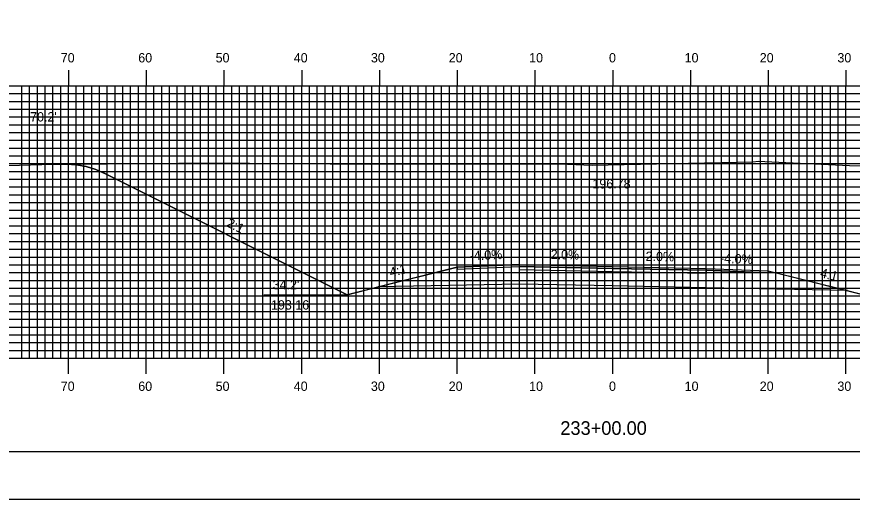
# Model space of a CAD drawing. Extents: x 1799962 to 1800305, y 442591 to 442811.
# Drawn here: x 1800050.9 to 1800158.3, y 442590.5 to 442652.5 of the extents above; entities that cross this region are included whole.
import ezdxf

# ---------------------------------------------------------------- set-up
doc = ezdxf.new("R2010")
doc.units = 0
for name, color, linetype in [('ANNOTATION', 7, 'Continuous'), ('BORDER', 7, 'Continuous'), ('D_Roadway_Centerline', 7, 'Continuous'), ('D_Roadway_Centerline_Text', 7, 'Continuous'), ('D_Roadway_Edge_Shoulder', 7, 'Continuous'), ('D_Roadway_Edge_TW', 7, 'Continuous'), ('D_Roadway_Pavement', 7, 'Continuous'), ('D_Roadway_SlopeLines', 7, 'Continuous'), ('D_Roadway_SubGrade', 7, 'Continuous'), ('D_Text_Standard', 7, 'Continuous'), ('H_V ANNOTATION', 7, 'Continuous'), ('MAJOR', 7, 'Continuous'), ('MINOR', 7, 'Continuous'), ('PDRAIN', 7, 'Continuous'), ('PLOT BOUNDARY', 7, 'Continuous'), ('S_Roadway_Centerline', 7, 'Continuous')]:
    doc.layers.add(name, color=color, linetype=linetype)

msp = doc.modelspace()

# ---------------------------------------------------------------- linework, layer by layer
at = {"layer": 'BORDER'}
msp.add_lwpolyline([(1799977.92, 442596.67), (1800297.92, 442596.67), (1800297.92, 442806.67), (1799977.92, 442806.67)], close=True, dxfattribs=at)
at = {"layer": 'D_Roadway_Centerline'}
msp.add_lwpolyline([(1800057.29, 442633.58), (1800058.54, 442633.51), (1800059.79, 442633.29), (1800061.04, 442632.9), (1800062.29, 442632.35), (1800093.35, 442616.83), (1800097.35, 442617.83), (1800107.52, 442620.37), (1800115.52, 442620.69), (1800127.52, 442620.45), (1800139.52, 442620.21), (1800147.52, 442619.89), (1800157.7, 442617.35), (1800161.7, 442616.35), (1800193.07, 442632.03), (1800194.32, 442632.58), (1800195.57, 442632.97), (1800196.82, 442633.21), (1800198.07, 442633.29)], dxfattribs=at)
at = {"layer": 'D_Roadway_Edge_Shoulder'}
for points in [[(1800115.52, 442620.69), (1800107.52, 442620.37), (1800107.52, 442620.12), (1800115.52, 442620.44)], [(1800139.52, 442620.21), (1800147.52, 442619.89), (1800147.52, 442619.64), (1800139.52, 442619.96)]]:
    msp.add_lwpolyline(points, close=True, dxfattribs=at)
at = {"layer": 'D_Roadway_Edge_TW'}
msp.add_lwpolyline([(1800115.52, 442620.44), (1800115.52, 442620.69), (1800127.52, 442620.45), (1800139.52, 442620.21), (1800139.52, 442619.96), (1800127.52, 442620.2)], close=True, dxfattribs=at)
at = {"layer": 'D_Roadway_Pavement'}
msp.add_lwpolyline([(1800115.52, 442620.02), (1800115.52, 442620.44), (1800127.52, 442620.2), (1800139.52, 442619.96), (1800139.52, 442619.54), (1800127.52, 442619.78)], close=True, dxfattribs=at)
at = {"layer": 'D_Roadway_SlopeLines'}
for points in [[(1800093.35, 442616.83), (1800062.29, 442632.35), (1800061.04, 442632.9), (1800059.79, 442633.29), (1800058.54, 442633.51), (1800057.29, 442633.58)], [(1800107.52, 442620.37), (1800093.35, 442616.83)], [(1800147.52, 442619.89), (1800161.7, 442616.35)]]:
    msp.add_lwpolyline(points, dxfattribs=at)
at = {"layer": 'D_Roadway_SubGrade'}
msp.add_lwpolyline([(1800115.52, 442618.19), (1800097.35, 442617.83), (1800107.52, 442620.37), (1800107.52, 442620.12), (1800115.52, 442620.44), (1800127.52, 442620.2), (1800139.52, 442619.96), (1800147.52, 442619.64), (1800147.52, 442619.89), (1800157.7, 442617.35), (1800139.52, 442617.71), (1800127.52, 442617.95)], close=True, dxfattribs=at)
at = {"layer": 'MAJOR'}
for p, q in [((1800057.52, 442645.67), (1800057.52, 442643.67)), ((1800067.52, 442645.67), (1800067.52, 442643.67)), ((1800077.52, 442645.67), (1800077.52, 442643.67)), ((1800087.52, 442645.67), (1800087.52, 442643.67)), ((1800097.52, 442645.67), (1800097.52, 442643.67)), ((1800107.52, 442645.67), (1800107.52, 442643.67)), ((1800117.52, 442645.67), (1800117.52, 442643.67)), ((1800127.52, 442645.67), (1800127.52, 442643.67)), ((1800137.52, 442645.67), (1800137.52, 442643.67)), ((1800147.52, 442645.67), (1800147.52, 442643.67)), ((1800157.52, 442645.67), (1800157.52, 442643.67)), ((1799987.52, 442643.67), (1800267.52, 442643.67)), ((1799987.52, 442643.67), (1800267.52, 442643.67)), ((1800057.52, 442608.67), (1800057.52, 442643.67)), ((1800067.52, 442608.67), (1800067.52, 442643.67)), ((1800077.52, 442608.67), (1800077.52, 442643.67)), ((1800087.52, 442608.67), (1800087.52, 442643.67)), ((1800097.52, 442608.67), (1800097.52, 442643.67)), ((1800107.52, 442608.67), (1800107.52, 442643.67)), ((1800117.52, 442608.67), (1800117.52, 442643.67)), ((1800127.52, 442608.67), (1800127.52, 442643.67)), ((1800137.52, 442608.67), (1800137.52, 442643.67)), ((1800147.52, 442608.67), (1800147.52, 442643.67)), ((1800157.52, 442608.67), (1800157.52, 442643.67)), ((1799987.52, 442638.67), (1800267.52, 442638.67)), ((1799987.52, 442633.67), (1800267.52, 442633.67)), ((1799987.52, 442628.67), (1800267.52, 442628.67)), ((1799987.52, 442623.67), (1800267.52, 442623.67)), ((1799987.52, 442618.67), (1800267.52, 442618.67)), ((1799987.52, 442613.67), (1800267.52, 442613.67)), ((1799987.52, 442608.67), (1800267.52, 442608.67)), ((1799987.52, 442608.67), (1800267.52, 442608.67)), ((1800057.52, 442606.66), (1800057.52, 442608.67)), ((1800067.52, 442606.66), (1800067.52, 442608.67)), ((1800077.52, 442606.66), (1800077.52, 442608.67)), ((1800087.52, 442606.66), (1800087.52, 442608.67)), ((1800097.52, 442606.66), (1800097.52, 442608.67)), ((1800107.52, 442606.66), (1800107.52, 442608.67)), ((1800117.52, 442606.66), (1800117.52, 442608.67)), ((1800127.52, 442606.66), (1800127.52, 442608.67)), ((1800137.52, 442606.66), (1800137.52, 442608.67)), ((1800147.52, 442606.66), (1800147.52, 442608.67)), ((1800157.52, 442606.66), (1800157.52, 442608.67))]:
    msp.add_line(p, q, dxfattribs=at)
at = {"layer": 'MINOR'}
for p, q in [((1800051.52, 442608.67), (1800051.52, 442643.67)), ((1800052.52, 442608.67), (1800052.52, 442643.67)), ((1800053.52, 442608.67), (1800053.52, 442643.67)), ((1800054.52, 442608.67), (1800054.52, 442643.67)), ((1800055.52, 442608.67), (1800055.52, 442643.67)), ((1800056.52, 442608.67), (1800056.52, 442643.67)), ((1800058.52, 442608.67), (1800058.52, 442643.67)), ((1800059.52, 442608.67), (1800059.52, 442643.67)), ((1800060.52, 442608.67), (1800060.52, 442643.67)), ((1800061.52, 442608.67), (1800061.52, 442643.67)), ((1800062.52, 442608.67), (1800062.52, 442643.67)), ((1800063.52, 442608.67), (1800063.52, 442643.67)), ((1800064.52, 442608.67), (1800064.52, 442643.67)), ((1800065.52, 442608.67), (1800065.52, 442643.67)), ((1800066.52, 442608.67), (1800066.52, 442643.67)), ((1800068.52, 442608.67), (1800068.52, 442643.67)), ((1800069.52, 442608.67), (1800069.52, 442643.67)), ((1800070.52, 442608.67), (1800070.52, 442643.67)), ((1800071.52, 442608.67), (1800071.52, 442643.67)), ((1800072.52, 442608.67), (1800072.52, 442643.67)), ((1800073.52, 442608.67), (1800073.52, 442643.67)), ((1800074.52, 442608.67), (1800074.52, 442643.67)), ((1800075.52, 442608.67), (1800075.52, 442643.67)), ((1800076.52, 442608.67), (1800076.52, 442643.67)), ((1800078.52, 442608.67), (1800078.52, 442643.67)), ((1800079.52, 442608.67), (1800079.52, 442643.67)), ((1800080.52, 442608.67), (1800080.52, 442643.67)), ((1800081.52, 442608.67), (1800081.52, 442643.67)), ((1800082.52, 442608.67), (1800082.52, 442643.67)), ((1800083.52, 442608.67), (1800083.52, 442643.67)), ((1800084.52, 442608.67), (1800084.52, 442643.67)), ((1800085.52, 442608.67), (1800085.52, 442643.67)), ((1800086.52, 442608.67), (1800086.52, 442643.67)), ((1800088.52, 442608.67), (1800088.52, 442643.67)), ((1800089.52, 442608.67), (1800089.52, 442643.67)), ((1800090.52, 442608.67), (1800090.52, 442643.67)), ((1800091.52, 442608.67), (1800091.52, 442643.67)), ((1800092.52, 442608.67), (1800092.52, 442643.67)), ((1800093.52, 442608.67), (1800093.52, 442643.67)), ((1800094.52, 442608.67), (1800094.52, 442643.67)), ((1800095.52, 442608.67), (1800095.52, 442643.67)), ((1800096.52, 442608.67), (1800096.52, 442643.67)), ((1800098.52, 442608.67), (1800098.52, 442643.67)), ((1800099.52, 442608.67), (1800099.52, 442643.67)), ((1800100.52, 442608.67), (1800100.52, 442643.67)), ((1800101.52, 442608.67), (1800101.52, 442643.67)), ((1800102.52, 442608.67), (1800102.52, 442643.67)), ((1800103.52, 442608.67), (1800103.52, 442643.67)), ((1800104.52, 442608.67), (1800104.52, 442643.67)), ((1800105.52, 442608.67), (1800105.52, 442643.67)), ((1800106.52, 442608.67), (1800106.52, 442643.67)), ((1800108.52, 442608.67), (1800108.52, 442643.67)), ((1800109.52, 442608.67), (1800109.52, 442643.67)), ((1800110.52, 442608.67), (1800110.52, 442643.67)), ((1800111.52, 442608.67), (1800111.52, 442643.67)), ((1800112.52, 442608.67), (1800112.52, 442643.67)), ((1800113.52, 442608.67), (1800113.52, 442643.67)), ((1800114.52, 442608.67), (1800114.52, 442643.67)), ((1800115.52, 442608.67), (1800115.52, 442643.67)), ((1800116.52, 442608.67), (1800116.52, 442643.67)), ((1800118.52, 442608.67), (1800118.52, 442643.67)), ((1800119.52, 442608.67), (1800119.52, 442643.67)), ((1800120.52, 442608.67), (1800120.52, 442643.67)), ((1800121.52, 442608.67), (1800121.52, 442643.67)), ((1800122.52, 442608.67), (1800122.52, 442643.67)), ((1800123.52, 442608.67), (1800123.52, 442643.67)), ((1800124.52, 442608.67), (1800124.52, 442643.67)), ((1800125.52, 442608.67), (1800125.52, 442643.67)), ((1800126.52, 442608.67), (1800126.52, 442643.67)), ((1800128.52, 442608.67), (1800128.52, 442643.67)), ((1800129.52, 442608.67), (1800129.52, 442643.67)), ((1800130.52, 442608.67), (1800130.52, 442643.67)), ((1800131.52, 442608.67), (1800131.52, 442643.67)), ((1800132.52, 442608.67), (1800132.52, 442643.67)), ((1800133.52, 442608.67), (1800133.52, 442643.67)), ((1800134.52, 442608.67), (1800134.52, 442643.67)), ((1800135.52, 442608.67), (1800135.52, 442643.67)), ((1800136.52, 442608.67), (1800136.52, 442643.67)), ((1800138.52, 442608.67), (1800138.52, 442643.67)), ((1800139.52, 442608.67), (1800139.52, 442643.67)), ((1800140.52, 442608.67), (1800140.52, 442643.67)), ((1800141.52, 442608.67), (1800141.52, 442643.67)), ((1800142.52, 442608.67), (1800142.52, 442643.67)), ((1800143.52, 442608.67), (1800143.52, 442643.67)), ((1800144.52, 442608.67), (1800144.52, 442643.67)), ((1800145.52, 442608.67), (1800145.52, 442643.67)), ((1800146.52, 442608.67), (1800146.52, 442643.67)), ((1800148.52, 442608.67), (1800148.52, 442643.67)), ((1800149.52, 442608.67), (1800149.52, 442643.67)), ((1800150.52, 442608.67), (1800150.52, 442643.67)), ((1800151.52, 442608.67), (1800151.52, 442643.67)), ((1800152.52, 442608.67), (1800152.52, 442643.67)), ((1800153.52, 442608.67), (1800153.52, 442643.67)), ((1800154.52, 442608.67), (1800154.52, 442643.67)), ((1800155.52, 442608.67), (1800155.52, 442643.67)), ((1800156.52, 442608.67), (1800156.52, 442643.67)), ((1799987.52, 442642.67), (1800267.52, 442642.67)), ((1799987.52, 442641.67), (1800267.52, 442641.67)), ((1799987.52, 442640.67), (1800267.52, 442640.67)), ((1799987.52, 442639.67), (1800267.52, 442639.67)), ((1799987.52, 442637.67), (1800267.52, 442637.67)), ((1799987.52, 442636.67), (1800267.52, 442636.67)), ((1799987.52, 442635.67), (1800267.52, 442635.67)), ((1799987.52, 442634.67), (1800267.52, 442634.67)), ((1799987.52, 442632.67), (1800267.52, 442632.67)), ((1799987.52, 442631.67), (1800267.52, 442631.67)), ((1799987.52, 442630.67), (1800267.52, 442630.67)), ((1799987.52, 442629.67), (1800267.52, 442629.67)), ((1799987.52, 442627.67), (1800267.52, 442627.67)), ((1799987.52, 442626.67), (1800267.52, 442626.67)), ((1799987.52, 442625.67), (1800267.52, 442625.67)), ((1799987.52, 442624.67), (1800267.52, 442624.67)), ((1799987.52, 442622.67), (1800267.52, 442622.67)), ((1799987.52, 442621.67), (1800267.52, 442621.67)), ((1799987.52, 442620.67), (1800267.52, 442620.67)), ((1799987.52, 442619.67), (1800267.52, 442619.67)), ((1799987.52, 442617.67), (1800267.52, 442617.67)), ((1799987.52, 442616.67), (1800267.52, 442616.67)), ((1799987.52, 442615.67), (1800267.52, 442615.67)), ((1799987.52, 442614.67), (1800267.52, 442614.67)), ((1799987.52, 442612.67), (1800267.52, 442612.67)), ((1799987.52, 442611.67), (1800267.52, 442611.67)), ((1799987.52, 442610.67), (1800267.52, 442610.67)), ((1799987.52, 442609.67), (1800267.52, 442609.67))]:
    msp.add_line(p, q, dxfattribs=at)
at = {"layer": 'PDRAIN'}
msp.add_line((1800082.63, 442616.83), (1800093.35, 442616.83), dxfattribs=at)
at = {"layer": 'PLOT BOUNDARY'}
msp.add_lwpolyline([(1799961.74, 442590.55), (1800301.74, 442590.55), (1800301.74, 442810.55), (1799961.74, 442810.55)], close=True, dxfattribs=at)
at = {"layer": 'S_Roadway_Centerline'}
msp.add_lwpolyline([(1799987.52, 442630.67), (1799991.56, 442630.77), (1800007.69, 442631.83), (1800014.08, 442632.16), (1800018.63, 442632.4), (1800023.9, 442632.56), (1800041.39, 442632.95), (1800049.75, 442633.44), (1800054.08, 442633.55), (1800057.92, 442633.59), (1800071.67, 442633.71), (1800080.81, 442633.72), (1800096.35, 442633.61), (1800103.47, 442633.65), (1800120.62, 442633.63), (1800124.86, 442633.46), (1800145.55, 442633.91), (1800146.28, 442633.97), (1800147.08, 442633.93), (1800157.96, 442633.42), (1800167.23, 442633.22)], dxfattribs=at)

# ---------------------------------------------------------------- texts
at = {"layer": 'ANNOTATION'}
for s, rotation, p in [('2:1', 333.4349, (1800077.75, 442625.66)), ('-4.0%', 2.2906, (1800109.15, 442621.24)), ('2.0%', 358.8542, (1800119.53, 442621.41)), ('-2.0%', 358.8542, (1800131.21, 442621.18)), ('-4.0%', 357.7094, (1800141.31, 442620.94)), ('4:1', 14.0362, (1800098.97, 442619.09)), ('4:1', 345.9638, (1800154.12, 442619.1))]:
    msp.add_text(s, height=1.2, rotation=rotation, dxfattribs=at).set_placement(p)
for s, p in [("34.2'", (1800083.79, 442617.52)), ('193.16', (1800083.57, 442614.92))]:
    msp.add_text(s, height=1.2, dxfattribs=at).set_placement(p)
at = {"layer": 'D_Roadway_Centerline'}
for s, p in [('C', (1800127.52, 442620.45)), ('L', (1800127.52, 442620.44))]:
    msp.add_text(s, height=0.0146, dxfattribs=at).set_placement(p)
at = {"layer": 'D_Roadway_Centerline_Text'}
msp.add_text('196.78', height=1.2, dxfattribs=at).set_placement((1800124.91, 442630.48))
at = {"layer": 'D_Text_Standard'}
msp.add_text("70.2'", height=1.2, dxfattribs=at).set_placement((1800052.59, 442639.08))
at = {"layer": 'H_V ANNOTATION'}
for s, height, p in [('70', 1.2, (1800056.53, 442646.67)), ('60', 1.2, (1800066.5, 442646.67)), ('50', 1.2, (1800076.45, 442646.67)), ('40', 1.2, (1800086.5, 442646.67)), ('30', 1.2, (1800096.42, 442646.67)), ('20', 1.2, (1800106.43, 442646.67)), ('10', 1.2, (1800116.77, 442646.67)), ('0', 1.2, (1800127.04, 442646.67)), ('10', 1.2, (1800136.77, 442646.67)), ('20', 1.2, (1800146.43, 442646.67)), ('30', 1.2, (1800156.42, 442646.67)), ('70', 1.2, (1800056.53, 442604.47)), ('60', 1.2, (1800066.5, 442604.47)), ('50', 1.2, (1800076.45, 442604.47)), ('40', 1.2, (1800086.5, 442604.47)), ('30', 1.2, (1800096.42, 442604.47)), ('20', 1.2, (1800106.43, 442604.47)), ('10', 1.2, (1800116.77, 442604.47)), ('0', 1.2, (1800127.04, 442604.47)), ('10', 1.2, (1800136.77, 442604.47)), ('20', 1.2, (1800146.43, 442604.47)), ('30', 1.2, (1800156.42, 442604.47)), ('233+00.00', 1.75, (1800120.78, 442598.82))]:
    msp.add_text(s, height=height, dxfattribs=at).set_placement(p)

doc.saveas('drawing.dxf')
